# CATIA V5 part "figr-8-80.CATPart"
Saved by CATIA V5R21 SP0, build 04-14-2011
Part number: Part1
Bounding box of the stored display mesh (mm): x -52.625 to 52.625, y -77.625 to 77.625, z 0 to 30
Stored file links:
  D:\CATIA V5R21 E-RESOURCES\CATIA-V5R21\catia-v5r21-prt\c08-catia-v5r20-prt\c08-catia-v5r21-figr-8-80.CATPart
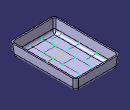
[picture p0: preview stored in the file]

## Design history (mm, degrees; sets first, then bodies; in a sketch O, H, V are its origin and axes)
Set1
  Plane1: type Offset, RefPlane xy-plane, Offset 30
  Plane2: type Offset, RefPlane face of Pad1, Offset -8, reversed
Body1 (main body)
  Sketch1 on xy-plane, origin (0, 0, 0), H (1, 0, 0), V (0, 1, 0)
    line L1 (-50, 75) -> (50, 75)
    line L2 (50, 75) -> (50, -75)
    line L3 (50, -75) -> (-50, -75)
    line L4 (-50, -75) -> (-50, 75)
    axis line L5 (50, -75) -> (-50, 75)
    length L3 = 100
    length L2 = 150
    horizontal: L1 H, L3 H
    vertical: L2 V, L4 V
    midpoint: O L5
  Pad1: profile Sketch1, direction (0, 0, 1), length 0, opposite side up to Plane1
  Draft1: Angle -5, Neutral face of Pad1, PullDir face of Pad1, SupportToDraft (face of Pad1; face of Pad1; face of Pad1; face of Pad1)
  Fillet1: radius 7, on edge [face of Pad1 | face of Pad1] (x4)
  Fillet2: radius 10, on edge [face of Pad1 | face of Pad1] (x4)
  Shell1: ExtOffset 0, Face face of Pad1, IntOffset 3
  Sketch2 on Plane2, origin (0, 0, 22), H (1, 0, 0), V (0, -1, 0)
    line L1 (28.1747, 54.0191) -> (28.1747, -59.2866)
    line L2 (0, 54.0191) -> (0, -59.2866)
    point P3 (0, 54.0191)
    line L3 (-9.5939, 0) -> (-33.0562, 0)
    point P5 (-9.5939, 0)
    line L4 (-9.5939, -40.4023) -> (-33.0562, -40.4023)
    point P7 (-9.5939, -40.4023)
    point P8 (-33.0562, -40.4023)
    point P9 (-33.0562, 40.4023)
    point P10 (-9.5939, 40.4023)
    line L5 (-9.5939, 40.4023) -> (-33.0562, 40.4023)
    line L6 (28.1747, 22.6983) -> (0, 22.6983)
    point P11 (28.1747, 22.6983)
    point P12 (0, 22.6983)
    point P13 (0, -22.6983)
    point P14 (28.1747, -22.6983)
    line L7 (28.1747, -22.6983) -> (0, -22.6983)
    line L8 (28.1747, 0) -> (41.8849, 0)
    point P15 (28.1747, 0)
    vertical: L1 V, L2 V
    coincidence: P3 V, P5 H, P11 L1, P12 L2, P15 L1, P15 H
    horizontal: L3 H, L4 H, L6 H, L8 H
    symmetry: P8 P9 L3, P7 P10 L3, L4 L5 L3, P12 P13 H, P11 P14 H, L6 L7 H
